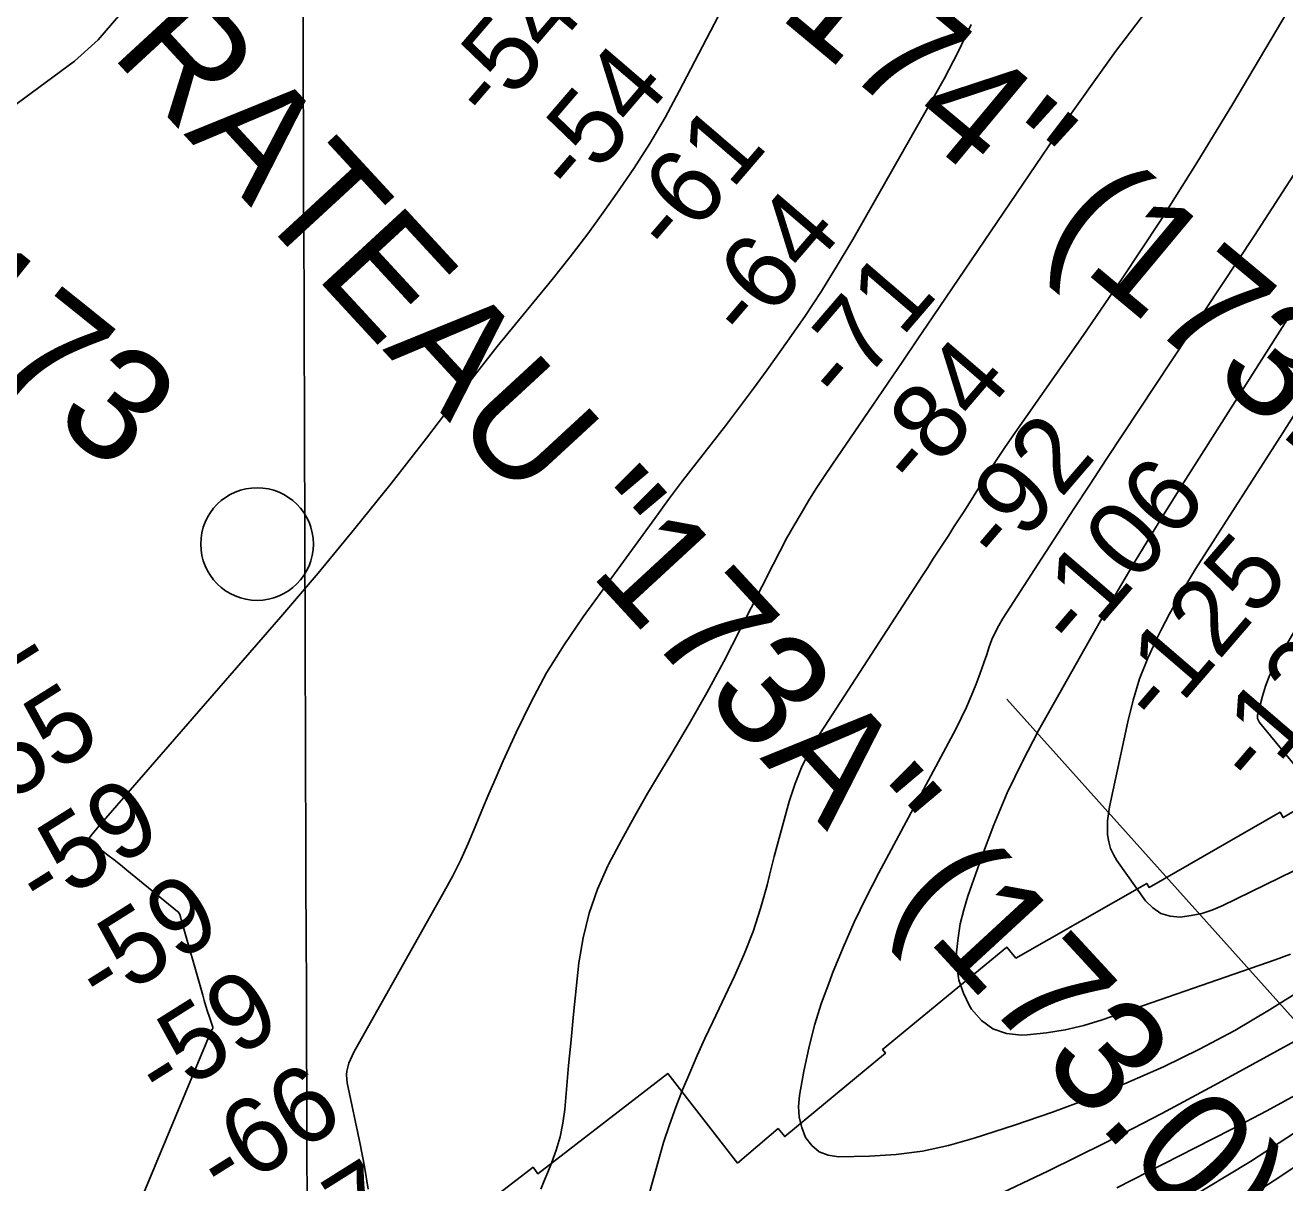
# Model space of a CAD drawing. Extents: x 3392644 to 3430565, y 576657 to 602123.
# Drawn here: x 3401788 to 3402906, y 585063 to 586091 of the extents above; entities that cross this region are included whole.
import ezdxf

# ---------------------------------------------------------------- set-up
doc = ezdxf.new("R2010")
doc.units = 0
for name, color, linetype in [('V-CHAN-NAID', 7, 'Continuous'), ('V-GRID-MAJR', 7, 'Continuous'), ('V-RIVR-EDGE', 7, 'Continuous'), ('V-RIVR-IDEN', 7, 'Continuous'), ('V-RIVR-MILE', 7, 'Continuous'), ('V-RIVR-RANG', 7, 'Continuous'), ('V-RRAP-RVMT', 7, 'Continuous'), ('V-TOPO-MAJR', 7, 'Continuous'), ('V-TOPO-MINR', 7, 'Continuous')]:
    doc.layers.add(name, color=color, linetype=linetype)

msp = doc.modelspace()

# ---------------------------------------------------------------- linework, layer by layer
at = {"layer": 'V-GRID-MAJR'}
msp.add_spline([(3402048.7, 582063.5), (3402028.4, 588122.7), (3402008.1, 594183.8), (3401987.8, 600244.9), (3401987.8, 600246.8)], degree=3, dxfattribs=at)
at = {"layer": 'V-RIVR-EDGE'}
msp.add_spline([(3396775.1, 583083.9), (3396813.1, 583077.3), (3396878.2, 583066.5), (3396944.3, 583054.6), (3397040.4, 583038.3), (3397098.9, 583026.5), (3397143.4, 583017.6), (3397248.7, 583000.1), (3397318.1, 582991.9), (3397366.7, 582985.6), (3397425.6, 582984), (3397482.6, 582983.5), (3397505.2, 582983.8), (3397523.2, 582984.1), (3397535.6, 582983), (3397547.3, 582984.4), (3397553.5, 582984.4), (3397557.5, 582982.9), (3397564.8, 582974.5), (3397565.1, 582965), (3397563.3, 582955.5), (3397562.9, 582944.2), (3397563.6, 582940.5), (3397567.6, 582939), (3397569.8, 582934.6), (3397572, 582924.8), (3397574.5, 582922.9), (3397581.5, 582921.5), (3397584.8, 582923.6), (3397587.7, 582927.3), (3397589.6, 582941.2), (3397592.5, 582951.4), (3397596.2, 582957.6), (3397599.9, 582960.9), (3397604.6, 582968.6), (3397610.5, 582971.8), (3397617.8, 582975.5), (3397652.6, 582980.5), (3397688, 582979.7), (3397709.9, 582978.5), (3397734.8, 582976.6), (3397757.8, 582975.9), (3397782.7, 582977.6), (3397809, 582980.8), (3397835.7, 582984.4), (3397884.7, 582992.4), (3397923.1, 582994.8), (3397953.4, 582993.6), (3397988.9, 582988.4), (3398024, 582990.2), (3398046.3, 582997.4), (3398058, 583005.8), (3398070.8, 583016), (3398086.2, 583024), (3398111.1, 583028.4), (3398172.5, 583041.7), (3398208, 583048.6), (3398231.4, 583047.8), (3398261.4, 583049.2), (3398287, 583052.4), (3398312.6, 583059.3), (3398337.8, 583067.6), (3398383.5, 583070.4), (3398451.1, 583073.6), (3398464.7, 583071), (3398479.3, 583062.2), (3398495.7, 583042), (3398503.3, 583028.1), (3398512.8, 583021.5), (3398522.7, 583021.5), (3398535.5, 583032.4), (3398552.7, 583039), (3398566.9, 583038.6), (3398581.9, 583033.4), (3398603.8, 583032.3), (3398616.3, 583032.2), (3398624.3, 583030), (3398639.7, 583030.3), (3398675.9, 583031.7), (3398691.9, 583032), (3398705.1, 583030.9), (3398713.5, 583032), (3398731.8, 583032.7), (3398752.3, 583033), (3398769.1, 583035.5), (3398785.2, 583035.1), (3398791, 583033.6), (3398807.1, 583027), (3398821, 583021.8), (3398831.5, 583014.5), (3398866.6, 582999.1), (3398896.9, 582982.5), (3398913.7, 582974.1), (3398926.5, 582974.8), (3398937.8, 582972.9), (3398949.9, 582968.9), (3398961.9, 582965.2), (3398977.3, 582966.6), (3398994.5, 582971), (3399010.9, 582975.7), (3399021.2, 582979.7), (3399028.9, 582985.9), (3399040.9, 582996.1), (3399048.3, 583000.1), (3399061.1, 583002.2), (3399090.7, 583006.2), (3399115.9, 583011.2), (3399122.1, 583011.2), (3399129.4, 583009.4), (3399136, 583003.2), (3399140.4, 582998.4), (3399145.1, 582998.4), (3399162, 582999.4), (3399171.5, 583000.1), (3399183.5, 582999.7), (3399192.3, 582999.7), (3399200.7, 583002.6), (3399201.8, 583006.6), (3399202.2, 583011.4), (3399199.7, 583018.3), (3399194.9, 583023.8), (3399194.6, 583028.6), (3399194.6, 583034.8), (3399197.9, 583043.2), (3399198.3, 583048.7), (3399196.5, 583062.2), (3399193.9, 583072.8), (3399193.6, 583076.1), (3399195.4, 583080.5), (3399198.3, 583083.1), (3399203.1, 583085.6), (3399213.3, 583087), (3399220.3, 583086.3), (3399226.9, 583079.7), (3399239.2, 583065.8), (3399254.9, 583052.9), (3399266.6, 583046.7), (3399276.1, 583046.7), (3399289.7, 583051), (3399302.5, 583058.7), (3399319.3, 583073.6), (3399325.9, 583081.3), (3399329.6, 583083.8), (3399336.9, 583081.6), (3399352.2, 583075), (3399367.9, 583071.3), (3399390.2, 583066.1), (3399402.6, 583065.7), (3399440.3, 583069.3), (3399461.5, 583073.6), (3399519.3, 583081.2), (3399573.1, 583094.9), (3399604.9, 583102.5), (3399633.4, 583107.6), (3399653.9, 583106.4), (3399671.1, 583108.6), (3399695.9, 583113.6), (3399715.3, 583122.4), (3399740.2, 583137.3), (3399751.6, 583151.1), (3399762.2, 583164.3), (3399774.7, 583175.9), (3399784.2, 583182.5), (3399792.6, 583189.1), (3399795.6, 583196), (3399799.6, 583197.4), (3399802.5, 583197.4), (3399809.5, 583193.8), (3399814.9, 583193.8), (3399821.9, 583194.1), (3399845.3, 583201.7), (3399905.6, 583216.6), (3399931.3, 583225.3), (3399967.5, 583235), (3399992.4, 583244.1), (3400000.4, 583253.2), (3400007.7, 583257.6), (3400018.3, 583260.5), (3400031.9, 583262.3), (3400048, 583265.2), (3400055.3, 583270.7), (3400066.6, 583276.1), (3400079.4, 583279), (3400083.8, 583280.5), (3400095.5, 583285.2), (3400101.4, 583285.5), (3400125.9, 583289.9), (3400153.7, 583298.6), (3400192.8, 583312), (3400239.7, 583327.6), (3400292, 583342.1), (3400327.1, 583352.2), (3400354.5, 583356.2), (3400375, 583360.9), (3400387.4, 583364.9), (3400390, 583364.1), (3400389.3, 583357.9), (3400389.2, 583356.1), (3400393.6, 583348.4), (3400397.2, 583337.8), (3400402, 583328.7), (3400413.6, 583316.6), (3400425, 583308.9), (3400439.2, 583307.4), (3400460.4, 583310.6), (3400467, 583315.3), (3400473.2, 583320.4), (3400475.5, 583330.7), (3400471.5, 583368.3), (3400471.6, 583380.4), (3400472.3, 583385.5), (3400478.2, 583390.2), (3400480.4, 583399), (3400481.5, 583402.7), (3400485.1, 583405.9), (3400498.3, 583410.7), (3400503.8, 583414.7), (3400508.2, 583419.4), (3400517, 583425.6), (3400522.9, 583431.8), (3400535.7, 583435.8), (3400564.6, 583444.1), (3400601.5, 583453.5), (3400634.1, 583462.2), (3400664.1, 583471.7), (3400688.6, 583481.8), (3400708, 583491.3), (3400725.9, 583502.6), (3400759.2, 583514.9), (3400794.3, 583529.1), (3400829.1, 583542.5), (3400869, 583559.3), (3400880.7, 583563.2), (3400906.7, 583575.6), (3400921, 583582.9), (3400934.5, 583585.8), (3400950.9, 583590.1), (3400981.3, 583603.2), (3401005.1, 583615.9), (3401022.7, 583620.7), (3401047.2, 583628.6), (3401067.7, 583634.8), (3401097.3, 583646.1), (3401115.6, 583651.5), (3401142.3, 583657.6), (3401149.6, 583661.6), (3401161.7, 583667.1), (3401193.5, 583681.6), (3401226.8, 583695.8), (3401250.2, 583702.3), (3401263.4, 583711.1), (3401269.3, 583717.3), (3401275.9, 583719.8), (3401292, 583724.2), (3401309.5, 583727.4), (3401322.7, 583735.8), (3401344.7, 583746.3), (3401352.7, 583750), (3401362.2, 583751.8), (3401379.4, 583760.5), (3401398.8, 583769.6), (3401425.2, 583782.3), (3401447.9, 583794), (3401460.3, 583801.6), (3401469.8, 583807.8), (3401481.2, 583811.8), (3401489.2, 583812.9), (3401505.3, 583824.9), (3401519.2, 583833.6), (3401536.8, 583842.7), (3401545.2, 583847.5), (3401556.2, 583853.6), (3401577.1, 583864.9), (3401601.2, 583877.3), (3401634.5, 583893.7), (3401648.8, 583904.6), (3401672.3, 583919.9), (3401702.7, 583940.7), (3401720.2, 583955.2), (3401724.6, 583960.7), (3401725.4, 583965.5), (3401725.8, 583971.7), (3401726.1, 583973.5), (3401728.7, 583974.2), (3401733.1, 583964.7), (3401734.9, 583964.7), (3401742.2, 583967.2), (3401756.1, 583975.6), (3401775.2, 583990.9), (3401800.4, 584006.2), (3401823.5, 584021.5), (3401859.4, 584047.4), (3401900, 584075.4), (3401938.1, 584104.2), (3401973.3, 584129.7), (3402017.6, 584163.2), (3402052, 584188.7), (3402068.5, 584206.2), (3402087.5, 584223.7), (3402105.1, 584237.2), (3402120.5, 584246.3), (3402139.9, 584263.4), (3402161.5, 584279.5), (3402205.1, 584317), (3402240.3, 584346.5), (3402249.4, 584352.7), (3402267, 584360.4), (3402279.1, 584369.8), (3402289.4, 584382.2), (3402295.6, 584388.4), (3402316.1, 584405.6), (3402366.3, 584439.1), (3402387.9, 584455.8), (3402402.5, 584467.9), (3402415, 584474.4), (3402428.1, 584479.9), (3402444.6, 584490.4), (3402463.7, 584506.1), (3402475.4, 584515.6), (3402490.4, 584526.9), (3402538.4, 584566.6), (3402565.9, 584589.9), (3402576.9, 584603.8), (3402584.2, 584615.5), (3402589, 584620.9), (3402605.1, 584634.1), (3402621.9, 584645), (3402632.5, 584652.6), (3402636.6, 584654.8), (3402639.1, 584654.1), (3402643.1, 584651.5), (3402646.1, 584651.9), (3402650.5, 584654.4), (3402655.2, 584657.3), (3402657.8, 584661), (3402658.2, 584663.5), (3402657.4, 584667.2), (3402657.8, 584669.8), (3402663.3, 584675.6), (3402665.1, 584682.2), (3402672.1, 584687.3), (3402682.4, 584693.5), (3402693.7, 584699.6), (3402701.8, 584708), (3402707.6, 584713.9), (3402719.3, 584722.6), (3402736.9, 584743), (3402754.5, 584764.2), (3402759, 584773.3), (3402762.3, 584784.6), (3402760.8, 584794.2), (3402761.6, 584796.3), (3402774.4, 584808.4), (3402790.2, 584827.7), (3402794.6, 584836.1), (3402801.9, 584838.6), (3402805.5, 584843), (3402807.8, 584848.9), (3402817.6, 584858.3), (3402830.1, 584866.4), (3402842.2, 584879.1), (3402850.3, 584889.7), (3402856.1, 584902.5), (3402862.7, 584909), (3402867.9, 584912.7), (3402878.8, 584918.9), (3402888.4, 584926.5), (3402904.5, 584941.5), (3402914.4, 584948.4), (3402928.3, 584956.4), (3402934.9, 584963), (3402937.8, 584966.6), (3402938.2, 584971.7), (3402937.5, 584981.2), (3402937.5, 584985.3), (3402953.2, 584998.4), (3402977.8, 585014.8), (3402996.1, 585025.3), (3403016.6, 585033.3), (3403039.6, 585040.2), (3403050.2, 585047.5), (3403059.8, 585052.2), (3403070.4, 585053.7), (3403078, 585055.1), (3403086.8, 585058.7), (3403115, 585071.5), (3403146.5, 585086.4), (3403132.2, 585079.8), (3403142.5, 585086), (3403170.3, 585097.6), (3403184.9, 585105.3), (3403217.1, 585117.3), (3403261, 585129.6), (3403315.5, 585137.9), (3403347.7, 585142.9), (3403378, 585148.3), (3403417.2, 585155.5), (3403455.2, 585164.9), (3403485.9, 585175.1), (3403512.3, 585188.5), (3403532.1, 585206), (3403547.1, 585222.5), (3403548.9, 585227.2), (3403552.2, 585230.5), (3403560.6, 585231.6), (3403567.2, 585229.7), (3403576, 585229.7), (3403592.1, 585238.4), (3403619.9, 585256.6), (3403671.5, 585292.3), (3403695.3, 585305.8), (3403703, 585308), (3403726.5, 585322.2), (3403748.1, 585336.4), (3403779.5, 585358.6), (3403809.2, 585377.5), (3403822.8, 585393.6), (3403849.2, 585429.7), (3403874.9, 585465.8), (3403895.4, 585495), (3403900.9, 585503.4), (3403902.7, 585503.8), (3403907.1, 585503.8), (3403912.2, 585507.4), (3403928.8, 585531.5), (3403948.9, 585557.8), (3403964.7, 585578.6), (3403972, 585584.8), (3403979.7, 585590.2), (3403995.5, 585610.3), (3404005, 585622.7), (3404016.4, 585633.6), (3404029.6, 585643.5), (3404038, 585651.5), (3404056, 585682.5), (3404090.1, 585725.6), (3404116.1, 585765.7), (3404146.2, 585804.4), (3404172.9, 585828.5), (3404201.2, 585866.4), (3404218.4, 585893), (3404241.9, 585935.8), (3404254.1, 585966.4), (3404273.2, 586011.3), (3404296, 586065.4), (3404324.7, 586140.3), (3404338.7, 586187), (3404345.7, 586217.7), (3404351.2, 586238.5), (3404360.5, 586263.7), (3404367.4, 586279.4), (3404369.3, 586292.9), (3404362.8, 586312.3), (3404363.2, 586329.9), (3404363.6, 586342.7), (3404369.1, 586353.6), (3404375.4, 586376.3), (3404378, 586402.6), (3404387.6, 586442.8), (3404404.9, 586483.7), (3404421.1, 586535.9), (3404432.5, 586570.6), (3404448.7, 586615.9), (3404459, 586653.9), (3404467.2, 586695.2), (3404471.3, 586726.6), (3404473.2, 586754.7), (3404478.8, 586815.4), (3404482.5, 586856), (3404480.8, 586876.8), (3404477.1, 586890.4), (3404476.4, 586897.3), (3404479.4, 586906.1), (3404487.1, 586917.7), (3404493.7, 586931.3), (3404496.7, 586951.7), (3404498.6, 586978.8), (3404518.4, 587033.9), (3404529.5, 587065.3), (3404542.7, 587101.1), (3404549.4, 587126.3), (3404556.4, 587159.6), (3404562.7, 587192.4), (3404572.3, 587229.7), (3404579, 587263), (3404583.8, 587291.5), (3404584.2, 587312.7), (3404584.3, 587365.7), (3404586.3, 587407.7), (3404589.7, 587479.7), (3404590.9, 587511.5), (3404590.2, 587522.5), (3404583.7, 587546.6), (3404570.6, 587590.5), (3404552.9, 587645), (3404544.1, 587665.5), (3404532.5, 587688.6), (3404524.9, 587703.2), (3404520.5, 587711.3), (3404519.8, 587718.2), (3404519.8, 587729.9), (3404518.7, 587740.9), (3404514, 587745.6), (3404512.2, 587750), (3404510, 587765.8)], degree=3, dxfattribs=at)
at = {"layer": 'V-RIVR-MILE'}
msp.add_circle((3401994.1, 585630.1), 50, dxfattribs=at)
at = {"layer": 'V-RIVR-RANG'}
msp.add_line((3403393.3, 584673.2), (3402659.2, 585492.4), dxfattribs=at)
at = {"layer": 'V-RRAP-RVMT'}
for points in [[(3402989.6, 585437.3), (3402904.6, 585387.3), (3402901.8, 585392.1), (3402785.5, 585325.3), (3402783.4, 585328.9), (3402667.4, 585262.7), (3402659.4, 585272.2), (3402549, 585181.4), (3402551.6, 585178.2), (3402462.3, 585104.3), (3402456.4, 585111.3), (3402420.3, 585080.6)], [(3402420.3, 585080.6), (3402358.5, 585160.2), (3402243.3, 585071.3), (3402238.9, 585077), (3402115.8, 584982.1), (3402134, 584958.5), (3402018.2, 584867), (3402025.7, 584857.7), (3401911.6, 584769.8), (3401949.9, 584720.3), (3401837.2, 584632.8), (3401877.7, 584581), (3401763.3, 584499)]]:
    msp.add_lwpolyline(points, dxfattribs=at)
at = {"layer": 'V-TOPO-MAJR'}
for points in [[(3401579.7, 585872.5), (3401832.1, 586058.7), (3401853.1, 586077.6), (3401871.2, 586098.6)], [(3402932, 585986), (3402878.9, 585904), (3402747.5, 585705.1), (3402733.1, 585683.3), (3402718.8, 585661.5), (3402704.5, 585639.6), (3402690.3, 585617.6), (3402655.6, 585563.9), (3402652.1, 585557.9), (3402648.8, 585551.7), (3402646.1, 585545.3), (3402643.7, 585538.8), (3402641.4, 585532.2), (3402639.2, 585525.5), (3402636.8, 585518.9), (3402634.4, 585512.4), (3402631.7, 585505.2), (3402627.7, 585495.2), (3402623.4, 585485.3), (3402618.8, 585475.6), (3402613.9, 585465.9), (3402545.8, 585338.4), (3402534.6, 585316.5), (3402523.9, 585294.4), (3402514.1, 585272), (3402504.7, 585249.3), (3402502.1, 585242.6), (3402495, 585222.9), (3402488.7, 585203), (3402483.6, 585182.8), (3402479.2, 585162.3), (3402475.3, 585140.6), (3402474.5, 585131), (3402475, 585121.6), (3402477.3, 585112.4), (3402480.8, 585103.4), (3402486.4, 585096.2), (3402492.9, 585090.7), (3402500.9, 585087.6), (3402509.8, 585086.2), (3402537.5, 585086.9), (3402561.1, 585088.4), (3402584.4, 585091.4), (3402607.4, 585096.3), (3402630.2, 585102.7), (3402666.2, 585114.4), (3402699.8, 585126), (3402733.1, 585138.3), (3402765.9, 585151.9), (3402798.4, 585166.2), (3402830.3, 585181.9), (3402861.6, 585198.5), (3402892.2, 585216.6), (3402922.2, 585235.5)]]:
    msp.add_lwpolyline(points, dxfattribs=at)
at = {"layer": 'V-TOPO-MINR'}
for points in [[(3403090.5, 586410.3), (3402859.7, 586020.7), (3402827.9, 585968.4), (3402795.3, 585916.7), (3402761.5, 585865.7), (3402727, 585815.2), (3402676.3, 585743), (3402666.6, 585729), (3402657, 585714.8), (3402647.6, 585700.6), (3402638.4, 585686.2), (3402621.6, 585659.7), (3402617, 585652.5), (3402612.4, 585645.3), (3402607.8, 585638.1), (3402603.1, 585630.9), (3402598.4, 585623.7), (3402593.7, 585616.6), (3402589.1, 585609.4), (3402584.4, 585602.2), (3402494, 585462.7), (3402485.4, 585448.2), (3402477.8, 585433.2), (3402471.6, 585417.7), (3402466.2, 585401.7), (3402461.7, 585385.4), (3402457.2, 585369.1), (3402452.9, 585352.7), (3402448.7, 585336.3), (3402446.5, 585327.3), (3402440.7, 585306.6), (3402434.1, 585286.2), (3402426.2, 585266.2), (3402417.6, 585246.5), (3402398.4, 585206.2), (3402391.4, 585191.2), (3402384.6, 585176.1), (3402378, 585160.9), (3402371.6, 585145.6), (3402365.5, 585130.2), (3402359.9, 585114.7), (3402354.8, 585099), (3402350.1, 585083.1), (3402328.6, 585005.9)], [(3402493.3, 586271.5), (3402368.7, 586031.9), (3402356, 586008.6), (3402342.6, 585985.7), (3402328.3, 585963.4), (3402313.4, 585941.4), (3402302.6, 585926.3), (3402287.4, 585905.5), (3402271.9, 585885), (3402256, 585864.9), (3402239.7, 585845), (3402223.3, 585825.2), (3402207.1, 585805.3), (3402191.2, 585785.1), (3402175.4, 585764.8), (3402144.4, 585724.2), (3402112.9, 585683.8), (3402080.9, 585643.8), (3402048.2, 585604.4), (3402015, 585565.4), (3401854, 585380.1), (3401850.8, 585376.3), (3401847.8, 585372.5), (3401844.8, 585368.7), (3401844.6, 585368.5), (3401844.4, 585367.8), (3401844.4, 585367.2), (3401844.7, 585366.6), (3401844.9, 585366.4), (3401855.9, 585358.3), (3401861.6, 585354), (3401867.3, 585349.7), (3401872.9, 585345.3), (3401878.5, 585340.8), (3401923.5, 585304), (3401924.5, 585303), (3401925.7, 585300.4), (3401926.1, 585299.1), (3401945.8, 585229.7), (3401947.2, 585224.9), (3401948.7, 585220), (3401950.2, 585215.1), (3401951.8, 585210.3), (3401954.8, 585201.2), (3401954.8, 585201), (3401954.8, 585200.4), (3401954.5, 585199.9), (3401954.1, 585199.4), (3401953.9, 585199.2), (3401802.8, 584836.4)], [(3403104.4, 586138.9), (3402815.9, 585684.3), (3402794.3, 585649.7), (3402773.1, 585614.8), (3402752.4, 585579.6), (3402732.2, 585544.2), (3402687.5, 585464.5), (3402673.1, 585437.2), (3402659.7, 585409.3), (3402647.7, 585380.9), (3402636.8, 585352), (3402624.8, 585317.7), (3402621.1, 585305.5), (3402618, 585293.1), (3402616, 585280.5), (3402614.6, 585267.8), (3402614.9, 585255.3), (3402616.7, 585243.1), (3402620.8, 585231.5), (3402626.3, 585220.2), (3402628, 585217.4), (3402636.8, 585207.4), (3402646.9, 585199.8), (3402658.9, 585195.8), (3402672.2, 585194.3), (3402677.4, 585194.6), (3402694.4, 585196.3), (3402711.1, 585198.9), (3402727.6, 585202.9), (3402744, 585207.8), (3402897.3, 585261), (3402911.1, 585266)], [(3402805.1, 586132.4), (3402755.6, 586067.1), (3402707.9, 586000.2), (3402593.5, 585831.7), (3402580.2, 585812.1), (3402566.9, 585792.5), (3402553.6, 585773), (3402540.3, 585753.4), (3402504.5, 585700.9), (3402497.3, 585690.1), (3402490.2, 585679.3), (3402483.4, 585668.4), (3402476.7, 585657.3), (3402470.2, 585646.2), (3402463.9, 585634.9), (3402457.8, 585623.5), (3402451.9, 585612.1), (3402422.8, 585554.2), (3402408.2, 585526), (3402393.1, 585498), (3402377.3, 585470.4), (3402361.1, 585443), (3402352.8, 585429.3), (3402340.6, 585408.8), (3402328.8, 585388.2), (3402317.4, 585367.3), (3402306.3, 585346.2), (3402305.4, 585344.5), (3402296.2, 585323.8), (3402288.6, 585302.6), (3402283.3, 585280.7), (3402279.6, 585258.3), (3402277.1, 585235.6), (3402274.8, 585212.8), (3402272.6, 585190.1), (3402270.5, 585167.3), (3402267, 585128.4), (3402265.3, 585116.1), (3402262.9, 585104), (3402259.4, 585092.2), (3402255.2, 585080.6), (3402252, 585072.6), (3402248.8, 585065.1), (3402245.7, 585057.5)], [(3402627.6, 586091.3), (3402616.2, 586066.9), (3402603.7, 586042.9), (3402522.6, 585900.3), (3402508.9, 585877.2), (3402494.8, 585854.4), (3402480, 585832.1), (3402464.8, 585810.1), (3402446.7, 585784.8), (3402434.5, 585768.1), (3402422.2, 585751.5), (3402409.6, 585735.1), (3402396.9, 585718.8), (3402384.2, 585702.5), (3402371.6, 585686.1), (3402359.2, 585669.5), (3402347, 585652.9), (3402283.3, 585565.4), (3402266.6, 585540.8), (3402251, 585515.7), (3402236.9, 585489.6), (3402223.9, 585462.9), (3402212.5, 585437.6), (3402206.1, 585423.1), (3402199.7, 585408.4), (3402193.6, 585393.7), (3402187.6, 585379), (3402181.5, 585364.3), (3402174.9, 585349.8), (3402167.8, 585335.6), (3402160.2, 585321.6), (3402080, 585179.1), (3402078.4, 585175.9), (3402076.9, 585172.7), (3402075.6, 585169.3), (3402074.5, 585165.9), (3402073.8, 585162.4), (3402073.4, 585158.9), (3402073.6, 585155.4), (3402074, 585151.9), (3402085.5, 585097.4), (3402089.3, 585077.6), (3402092.5, 585057.7)], [(3402950.5, 585802.1), (3402904.1, 585728.7), (3402827.1, 585608.3), (3402819, 585595.2), (3402811.2, 585581.9), (3402803.7, 585568.3), (3402796.6, 585554.7), (3402792.6, 585546.8), (3402784.4, 585528.8), (3402777.1, 585510.4), (3402771.3, 585491.6), (3402766.5, 585472.4), (3402750.5, 585396.9), (3402749.4, 585390.7), (3402748.7, 585384.5), (3402748.5, 585378.3), (3402748.7, 585372), (3402749.7, 585365.9), (3402751.2, 585360), (3402753.8, 585354.5), (3402756.9, 585349.2), (3402782.4, 585313.6), (3402788.7, 585307.1), (3402795.9, 585302.3), (3402804.2, 585299.9), (3402813.2, 585299.1), (3402822.8, 585300.3), (3402832.2, 585302.3), (3402841.3, 585305.3), (3402850.3, 585309), (3402977.5, 585371)], [(3403021.3, 585733.2), (3402900.2, 585528.9), (3402895.8, 585520.8), (3402892, 585512.5), (3402888.8, 585503.9), (3402886.1, 585495.1), (3402881.9, 585479.1), (3402881.7, 585478.1), (3402881.8, 585475.2), (3402883.5, 585471.7), (3402939, 585404.3)], [(3402644.5, 585049.2), (3402695.7, 585073.6), (3402746.5, 585098.7), (3402796.9, 585124.8), (3402846.9, 585151.6), (3403121, 585301.8)], [(3402819.8, 585015.7), (3402900.6, 585068), (3403147.1, 585233)], [(3402756.9, 585058.7), (3402826.5, 585094.2), (3402858.2, 585110.6), (3402889.9, 585127.2), (3402921.4, 585144.3)], [(3402816.5, 585046.7), (3402875.6, 585082.2), (3402933.3, 585119.8)]]:
    msp.add_lwpolyline(points, dxfattribs=at)

# ---------------------------------------------------------------- texts
at = {"layer": 'V-CHAN-NAID'}
for s, rotation, p in [('BRINGIER POINT "174" (173.7)', 320.1944, (3401551.3, 586852.3)), ('RATEAU "173A" (173.0)', 312.6962, (3401863.1, 586064.8))]:
    msp.add_text(s, height=100, rotation=rotation, dxfattribs=at).set_placement(p)
at = {"layer": 'V-RIVR-IDEN'}
msp.add_text('173', height=100, rotation=321.2773, dxfattribs=at).set_placement((3401695.2, 585831.7))
at = {"layer": 'V-RIVR-RANG'}
for s, rotation, p in [('-54', 49.3433, (3402201.5, 586002.1)), ('-54', 49.3433, (3402277.2, 585936.8)), ('-61', 49.3433, (3402363.2, 585883.4)), ('-64', 49.3433, (3402429.9, 585807.7)), ('-71', 49.3433, (3402514.2, 585752.4)), ('-84', 49.3433, (3402580.7, 585676.2)), ('-92', 49.3433, (3402655.2, 585609.5)), ('-106', 49.3433, (3402721.9, 585533.7)), ('-125', 49.3433, (3402795.2, 585465.6)), ('-52', 32.1521, (3401694.8, 585469.2)), ('-131', 49.3433, (3402880.7, 585411.7)), ('-55', 32.1521, (3401748.7, 585385)), ('-59', 32.1521, (3401803.3, 585301.2)), ('-59', 32.1521, (3401856.3, 585216.4)), ('-59', 32.1521, (3401909.3, 585131.6)), ('-66', 32.1521, (3401963.9, 585047.8)), ('-67', 32.1521, (3402014.7, 584961.6))]:
    msp.add_text(s, height=67, rotation=rotation, dxfattribs=at).set_placement(p)

doc.saveas('drawing.dxf')
